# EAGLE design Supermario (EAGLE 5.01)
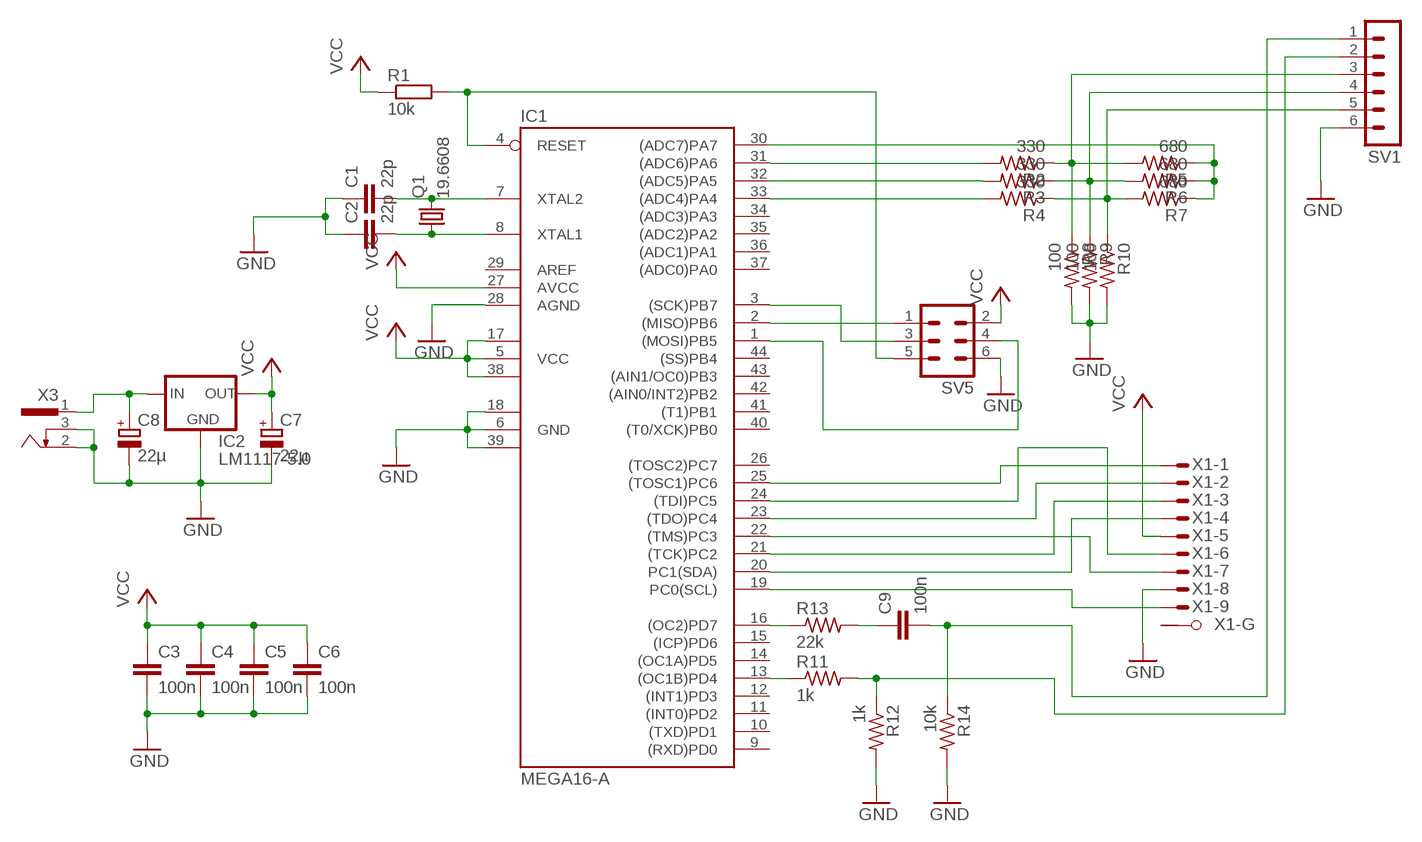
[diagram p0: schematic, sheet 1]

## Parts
C1  22p  C-EUC0805  [C0805]
C2  22p  C-EUC0805  [C0805]
C3  100n  C-EUC0805  [C0805]
C4  100n  C-EUC0805  [C0805]
C5  100n  C-EUC0805  [C0805]
C6  100n  C-EUC0805  [C0805]
C7  22µ  CPOL-EUE5-6  [E5-6]
C8  22µ  CPOL-EUE2-4  [E2-4]
C9  100n  C-EUC1206  [C1206]
IC1  MEGA16-A  [TQFP44]
IC2  LM1117-5.0  LM1117TO252  [TO252]
Q1  19.6608  CRYSTALSM49  [SM49]
R1  10k  R-EU_R0805  [R0805]
R2  330  R-US_0207/7  [0207/7]
R3  330  R-US_0207/7  [0207/7]
R4  330  R-US_0207/7  [0207/7]
R5  680  R-US_0207/7  [0207/7]
R6  680  R-US_0207/7  [0207/7]
R7  680  R-US_0207/7  [0207/7]
R8  100  R-US_0207/7  [0207/7]
R9  100  R-US_0207/7  [0207/7]
R10  100  R-US_0207/7  [0207/7]
R11  1k  R-US_0207/10  [0207/10]
R12  1k  R-US_0207/7  [0207/7]
R13  22k  R-US_0207/10  [0207/10]
R14  10k  R-US_0207/7  [0207/7]
SV1  MA06-1  [MA06-1]
SV5  MA03-2  [MA03-2]
X1  M09HPS  [M09HP]
X3  733980-62  [733980-62]

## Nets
GND: C1.1 C2.1 C3.2 C4.2 C5.2 C6.2 C7.- C8.- IC1.6(GND) IC1.18(GND1) IC1.28(AGND) IC1.39(GND2) IC2.1(GND) R8.2 R9.2 R10.2 R12.2 R14.2 SV1.6 SV5.6 X1.8(-8:M) X3.2 X3.3
N$1: C1.2 IC1.7(XTAL2) Q1.2
N$2: C2.2 IC1.8(XTAL1) Q1.1
N$3: IC1.19(PC0(SCL)) X1.9(-9:M)
N$4: IC1.20(PC1(SDA)) X1.4(-4:M)
N$5: IC1.21((TCK)PC2) X1.3(-3:M)
N$6: IC1.22((TMS)PC3) X1.7(-7:M)
N$7: IC1.23((TDO)PC4) X1.2(-2:M)
N$8: IC1.24((TDI)PC5) X1.6(-6:M)
N$9: R2.1 R5.2 R8.1 SV1.3
N$10: R3.1 R6.2 R9.1 SV1.4
N$11: R4.1 R7.2 R10.1 SV1.5
N$12: IC1.31((ADC6)PA6) R2.2
N$13: IC1.32((ADC5)PA5) R3.2
N$14: IC1.33((ADC4)PA4) R4.2
N$15: IC1.30((ADC7)PA7) R5.1 R6.1 R7.1
N$16: IC1.25((TOSC1)PC6) X1.1(-1:M)
N$17: IC1.2((MISO)PB6) SV5.1
N$18: IC1.3((SCK)PB7) SV5.3
N$19: IC1.4(RESET) R1.2 SV5.5
N$20: IC1.1((MOSI)PB5) SV5.4
N$21: IC1.16((OC2)PD7) R13.1
N$22: C8.+ IC2.2(IN) X3.1
N$23: C9.1 R13.2
N$24: IC1.13((OC1B)PD4) R11.1
N$25: R11.2 R12.1 SV1.2
N$26: C9.2 R14.1 SV1.1
VCC: C3.1 C4.1 C5.1 C6.1 C7.+ IC1.5(VCC) IC1.17(VCC1) IC1.27(AVCC) IC1.38(VCC2) IC2.3(OUT) R1.1 SV5.2 X1.5(-5:M)
Unconnected: IC1.9((RXD)PD0) IC1.10((TXD)PD1) IC1.11((INT0)PD2) IC1.12((INT1)PD3) IC1.14((OC1A)PD5) IC1.15((ICP)PD6) IC1.26((TOSC2)PC7) IC1.29(AREF) IC1.34((ADC3)PA3) IC1.35((ADC2)PA2) IC1.36((ADC1)PA1) IC1.37((ADC0)PA0) IC1.40((T0/XCK)PB0) IC1.41((T1)PB1) IC1.42((AIN0/INT2)PB2) IC1.43((AIN1/OC0)PB3) IC1.44((SS)PB4) X1.G1(-G:G1) X1.G2(-G:G2)

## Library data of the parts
C1-C6 C9 = rcl:C-EU: CAPACITOR, European symbol
C7 C8 = rcl:CPOL-EU: POLARIZED CAPACITOR, European symbol
IC1 = atmel:MEGA16: MICROCONTROLLER 16 Kbytes FLASH 1 kbytes SRAM 512 bytes EEPROM USART 8-channel 10 bit ADC Source: avr.lbr
IC2 = v-reg-2:LM1117
Q1 = crystal:CRYSTAL: CRYSTAL
R1 = rcl:R-EU_: RESISTOR, European symbol
R2-R14 = rcl:R-US_: RESISTOR, American symbol
SV1 = con-lstb:MA06-1: PIN HEADER
SV5 = con-lstb:MA03-2: PIN HEADER
X1 = con-subd:M09HPS: SUB-D
X3 = con-conrad:73398?: FEMALE PRINT CONNECTOR Niedervolt-Steckverbinder Distributor Conrad

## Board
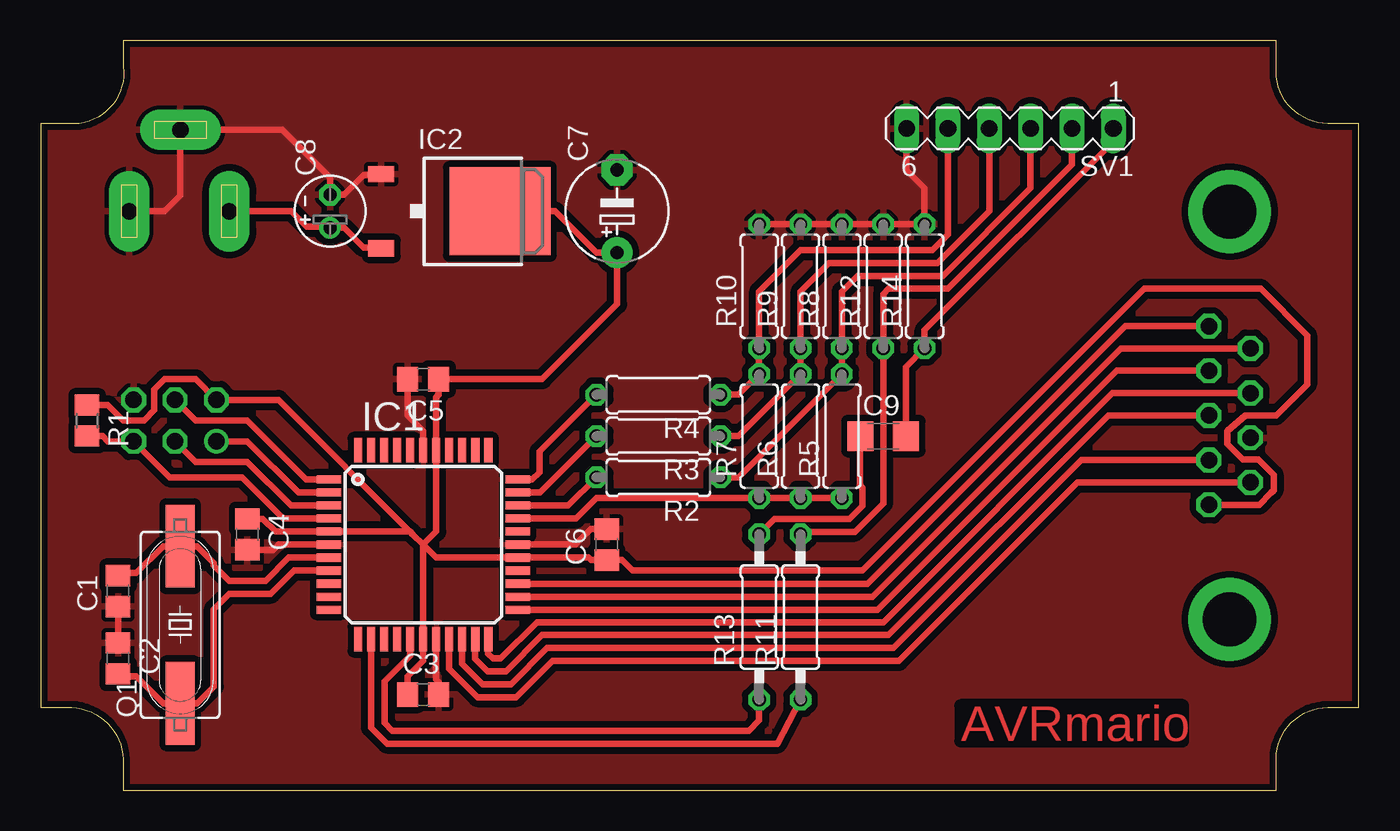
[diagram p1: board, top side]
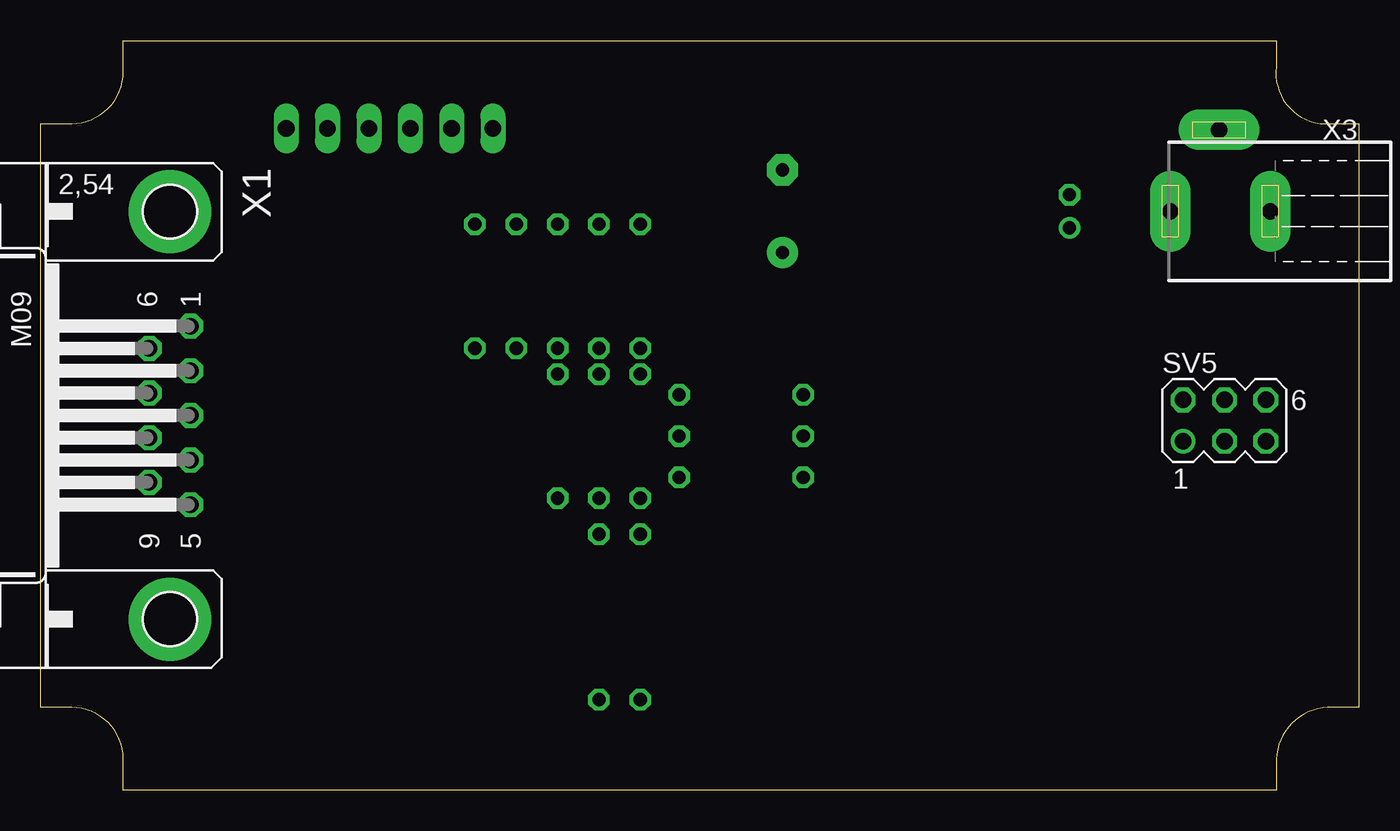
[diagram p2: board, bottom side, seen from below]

Size 80.95 x 46.04 mm. Coordinates in mm from the lower left corner, seen from the top.
Outline: 80.95,40.95 79.06,40.95 arc-90 75.88,44.13 75.88,46.04 5.07,46.04 5.07,44.45 arc-90 2.37,40.95 0,40.95 0,5.08 1.89,5.08 arc-90 5.07,1.59 5.07,0 75.88,0 75.88,1.91 arc-90 79.06,5.08 80.95,5.08 80.95,40.95
Copper layers (1*16): Top 0.035mm / dielectric 1.5mm / Bottom 0.035mm
Design rules "default *": minimum track width 10mil, minimum drill 24mil, track to track 8mil, track to pad 8mil, pad to pad 8mil, via to via 8mil, smd to smd 8mil, copper to edge 10mil, drill to drill 8mil, minimum pad ring 10mil, minimum via ring 8mil, stop-mask expansion 4mil, vias tented up to drill 0mil, thermal gap 10mil

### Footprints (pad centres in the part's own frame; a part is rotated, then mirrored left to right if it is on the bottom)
C0805 = smd 1.3 x 1.5: 1 -0.95,0; 2 0.95,0
E5-6 = drill 0.813 pad 1.905 round: + -2.54,0 | drill 0.813 pad 1.905 octagon: - 2.54,0
E2-4 = drill 0.813 pad 1.27 round: + -1.016,0 | drill 0.813 pad 1.27 octagon: - 1.016,0
C1206 = smd 1.6 x 1.8: 1 -1.4,0; 2 1.4,0
TQFP44 = smd 1.5 x 0.5: 1 -5.8,4; 2 -5.8,3.2; 3 -5.8,2.4; 4 -5.8,1.6; 5 -5.8,0.8; 6 -5.8,0; 7 -5.8,-0.8; 8 -5.8,-1.6; 9 -5.8,-2.4; 10 -5.8,-3.2; 11 -5.8,-4; 23 5.8,-4; 24 5.8,-3.2; 25 5.8,-2.4; 26 5.8,-1.6; 27 5.8,-0.8; 28 5.8,0; 29 5.8,0.8; 30 5.8,1.6; 31 5.8,2.4; 32 5.8,3.2; 33 5.8,4 | smd 0.5 x 1.5: 12 -4,-5.8; 13 -3.2,-5.8; 14 -2.4,-5.8; 15 -1.6,-5.8; 16 -0.8,-5.8; 17 0,-5.8; 18 0.8,-5.8; 19 1.6,-5.8; 20 2.4,-5.8; 21 3.2,-5.8; 22 4,-5.8; 34 4,5.8; 35 3.2,5.8; 36 2.4,5.8; 37 1.6,5.8; 38 0.8,5.8; 39 0,5.8; 40 -0.8,5.8; 41 -1.6,5.8; 42 -2.4,5.8; 43 -3.2,5.8; 44 -4,5.8
TO252 = smd 1 x 1.6: 1 -2.28,-6.07; 2 2.28,-6.07 | smd 5.4 x 6.2: 3 0,1.23
SM49 = smd 5.08 x 1.778: 1 -4.826,0; 2 4.826,0
R0805 = smd 1.3 x 1.5: 1 -0.95,0; 2 0.95,0
0207/7 = drill 0.813 octagon: 1 -3.81,0; 2 3.81,0
0207/10 = drill 0.813 octagon: 1 -5.08,0; 2 5.08,0
MA06-1 = drill 1.016 long: 1 -6.35,0; 2 -3.81,0; 3 -1.27,0; 4 1.27,0; 5 3.81,0; 6 6.35,0
MA03-2 = drill 1.016 round: 1 -2.54,-1.27 | drill 1.016 octagon: 2 -2.54,1.27; 3 0,-1.27; 4 0,1.27; 5 2.54,-1.27; 6 2.54,1.27
M09HP = drill 1.016 octagon: 1 -5.486,1.27; 2 -2.743,1.27; 3 0,1.27; 4 2.743,1.27; 5 5.486,1.27; 6 -4.115,-1.27; 7 -1.372,-1.27; 8 1.372,-1.27; 9 4.115,-1.27 | drill 3.302 pad 5.08 round: G1 -12.522,0; G2 12.522,0
733980-62 = drill 1 pad 2.5 long: 1 0,8.57; 2 0,2.42; 3 5,5.57

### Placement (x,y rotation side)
C1  4.76,12.22 90 top
C2  4.76,8.1 270 top
C3  23.49,5.87 0 top
C4  12.69,15.72 270 top
C5  23.49,25.24 180 top
C6  34.76,15.08 90 top
C7  35.39,35.56 90 top
C8  17.77,35.56 90 top
C9  51.75,21.75 0 top
IC1  23.49,15.08 0 top
IC2  26.98,35.56 270 top
Q1  8.57,10.16 90 top
R1  2.85,22.7 270 top
R2  37.93,19.21 180 top
R3  37.93,21.75 180 top
R4  37.93,24.29 180 top
R5  49.21,21.75 90 top
R6  46.67,21.75 90 top
R7  44.13,21.75 90 top
R8  49.21,30.96 90 top
R9  46.67,30.96 90 top
R10  44.13,30.96 90 top
R11  46.67,10.64 90 top
R12  51.75,30.96 90 top
R13  44.13,10.64 90 top
R14  54.29,30.96 90 top
SV1  59.52,40.64 180 top
SV5  8.25,22.7 0 bottom
X1  73.02,23.02 270 bottom
X3  3.01,35.56 90 bottom

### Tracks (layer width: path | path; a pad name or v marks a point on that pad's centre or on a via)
GND
  Top 0.406: IC1.39 23.49,22.07 22.54,23.02 C5.2 | IC1.6 14.6,15.08 14.28,14.76 C4.2 | 46.82,34.77 | 46.82,34.77 R9.2 R8.2 | R10.2 46.82,34.77 | 46.82,34.77 | R8.2 | R8.2 | R12.2 | R8.2 R12.2 | R12.2 | R12.2 R14.2 54.29,36.99 53.17,38.1 SV1.6 | C2.1 C1.1 | X3.2 7.61,35.56 8.57,36.51 8.57,40.48 8.58,40.49 X3.3 14.84,40.56 17.77,37.62 C8.- 18.63,36.58 19.84,37.78 20.79,37.78 20.85,37.84 IC2.1 | IC1.18 24.29,6.82 24.44,6.67 C3.2 | IC1.28 32.85,15.08 33.81,16.03 34.6,16.03 C6.2
  pour Top (isolate 0.406): 80.96,40.96 78.58,40.96 arc-90 75.88,44.29 75.88,46.04 5.07,46.04 arc-180 5.07,46.04 5.07,43.5 arc-90 2.85,40.96 0.15,40.96 0.15,5.08 2.22,5.08 arc-90 5.07,2.06 5.07,0.16 75.88,0.16 arc-90 76.04,0.32 76.04,1.91 arc-90 78.42,5.08 80.96,5.08
N$1
  Top 0.406: C1.2 4.76,13.34 5.87,13.34 7.52,14.99 Q1.2 9.61,14.99 10.63,13.97 10.63,13.81 11.58,12.86 13.8,12.86 15.23,14.29 17.61,14.29 17.62,14.28 IC1.7
N$2
  Top 0.406: C2.2 4.76,6.99 5.87,6.99 7.52,5.33 Q1.1 9.61,5.33 10.63,6.35 10.63,11.11 11.58,12.06 14.12,12.06 15.55,13.49 17.61,13.49 17.63,13.48 IC1.8
N$3
  Top 0.406: IC1.19 25.09,7.45 26.82,5.71 29.2,5.71 31.43,7.94 52.7,7.94 63.65,18.89 | 63.65,18.89 | X1.9 63.67,18.9 63.65,18.89
N$4
  Top 0.406: IC1.20 25.89,7.76 27.14,6.51 28.89,6.51 31.11,8.73 52.38,8.73 63.93,20.28 X1.4
N$5
  Top 0.406: IC1.21 26.69,8.07 27.46,7.3 28.57,7.3 30.79,9.53 52.06,9.53 65.56,23.02 X1.3
N$6
  Top 0.406: IC1.22 27.49,8.38 27.77,8.1 28.25,8.1 30.47,10.32 51.75,10.32 65.82,24.39 X1.7
N$7
  Top 0.406: X1.2 66.08,25.76 51.4,11.08 IC1.23
N$8
  Top 0.406: X1.6 66.34,27.13 51.11,11.91 | 51.11,11.91 | IC1.24 51.09,11.88 51.11,11.91
N$9
  Top 0.406: R8.1 | R5.2 R8.1 | R5.2 | R2.1 42.86,19.21 R5.2 | R8.1 49.21,30.64 50.16,31.59 55.4,31.59 60.79,36.99 | SV1.3 | 60.79,36.99 SV1.3 | 60.79,36.99
N$10
  Top 0.406: R9.1 | R6.2 R9.1 | R6.2 | R3.1 42.86,21.75 R6.2 | R9.1 46.67,30.64 48.41,32.38 55.08,32.38 58.25,35.56 SV1.4 | SV1.4 | SV1.4
N$11
  Top 0.406: R10.1 | R7.2 R10.1 | R7.2 | R4.1 42.86,24.29 R7.2 | R10.1 44.13,30.64 46.67,33.18 54.76,33.18 55.71,34.13 SV1.5 | SV1.5 | SV1.5
N$12
  Top 0.406: R2.2 | R2.2 | IC1.31 32.4,17.48 R2.2
N$13
  Top 0.406: R3.2 | IC1.32 30.66,18.28 R3.2
N$14
  Top 0.406: IC1.33 30.19,19.08 30.63,19.53 30.63,20.8 R4.2
N$15
  Top 0.406: R6.1 | R5.1 R6.1 | R7.1 R6.1 | R7.1 | R7.1 | IC1.30 32.87,16.68 34.12,17.94 42.39,17.95 R7.1
N$16
  Top 0.406: X1.1 66.6,28.5 50.77,12.68 IC1.25
N$17
  Top 0.406: IC1.2 15.84,18.28 12.69,21.43 SV5.1
N$18
  Top 0.406: IC1.3 15.37,17.48 12.69,20.16 9.52,20.16 SV5.3
N$19
  Top 0.406: IC1.4 14.9,16.68 12.38,19.21 7.93,19.21 SV5.5 4.12,21.43 3.8,21.75 R1.2
N$20
  Top 0.406: IC1.1 16.31,19.08 12.69,22.7 9.52,22.7 SV5.4
N$21
  Top 0.406: IC1.16 22.69,8.25 21.11,6.67 21.11,4.13 21.58,3.65 43.49,3.65 44.13,4.29 | 44.13,4.29 | 44.13,4.29 R13.1
N$22
  Top 0.406: X3.1 15.39,35.56 16.34,34.61 17.77,34.61 C8.+ 18.63,34.54 19.84,33.34 20.95,33.34 20.91,33.3 IC2.2
N$23
  Top 0.406: C9.1 50.32,21.72 50.32,18.73 50.48,18.57 50.48,17.46 49.68,16.67 45.08,16.67 R13.2 | R13.2
N$24
  Top 0.406: IC1.13 20.29,3.83 21.27,2.86 42.7,2.86 45.24,2.86 R11.1
N$25
  Top 0.406: R12.1 51.75,30.48 52.06,30.8 55.71,30.8 63.33,38.42 SV1.2 | SV1.2 | SV1.2 | R12.1 | R12.1 51.75,17.62 50,15.88 46.82,15.88 R11.2 | R11.2
N$26
  Top 0.406: SV1.1 | 65.87,40.48 | 65.87,40.48 SV1.1 | 65.87,40.48 65.87,39.85 54.29,28.26 R14.1 53.15,26.01 C9.2
VCC
  Top 0.406: C5.1 24.44,24.29 24.29,24.12 IC1.38 24.29,15.88 23.49,15.08 | 22.85,15.72 23.49,15.08 | 22.85,15.72 22.69,15.88 IC1.5 14.43,15.88 13.65,16.67 C4.1 | 23.49,15.08 IC1.17 23.49,7.94 22.54,6.99 C3.1 | 23.49,15.08 24.29,14.28 IC1.27 33.65,14.28 33.81,14.13 C6.1 34.92,14.13 35.71,14.13 36.35,13.49 50.48,13.49 67.78,30.8 74.92,30.8 77.78,27.94 77.78,24.92 75.88,23.02 73.97,23.02 72.86,22.07 72.86,21.27 73.81,20.32 74.76,20.32 75.72,19.37 75.72,18.41 75.56,18.26 | C5.1 | 22.85,15.72 14.6,23.97 SV5.2 9.52,25.24 7.61,25.24 6.98,24.61 6.98,23.34 6.34,22.7 5.07,22.7 4.12,23.65 R1.1 | IC2.3 31.58,35.56 34.12,33.02 35.24,33.02 | C3.1 | C3.1 | C5.1 30.79,25.24 35.39,29.84 35.39,32.86 35.24,33.02 | 35.24,33.02 C7.+ 35.39,33.18 | X1.5 74.83,17.53 75.56,18.26 | 75.56,18.26

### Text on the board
Top: AVRmario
